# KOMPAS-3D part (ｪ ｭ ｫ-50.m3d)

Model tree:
1. Эскиз:1
2. Операция выдавливания:1
     Расстояние 1 = 1
3. Эскиз:2
4. Операция выдавливания:2
     Расстояние 1 = 2
5. Эскиз:3
6. Вырезать элемент выдавливания:1
     Расстояние 1 = 200
7. Эскиз:4
8. Операция выдавливания:3
     Расстояние 1 = 5
9. Эскиз:5
10. Операция выдавливания:4
     Расстояние 1 = 1
11. Эскиз:6
12. Операция выдавливания:5
     Расстояние 1 = 9
13. Эскиз:7
14. Операция выдавливания:6
     Расстояние 1 = 9; Расстояние 2 = 200
15. Эскиз:8
16. Вырезать элемент выдавливания:2
     Расстояние 1 = 10
